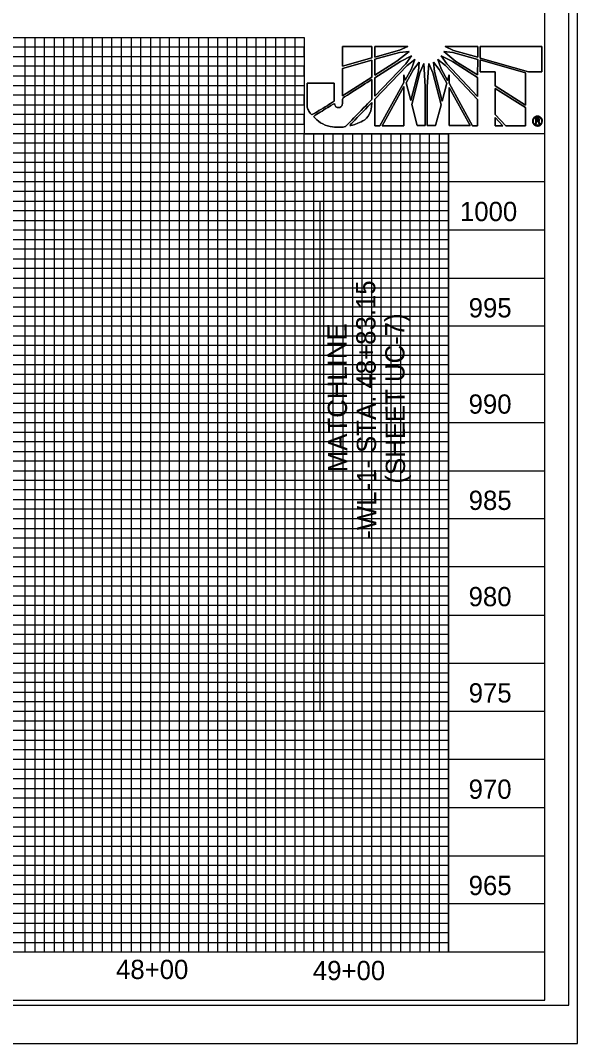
# Model space of a CAD drawing. Extents: x 0 to 7954, y -383 to 1504.
# Drawn here: x 2.351 to 2.833, y 0.008 to 0.894 of the extents above; entities that cross this region are included whole.
import ezdxf

# ---------------------------------------------------------------- set-up
doc = ezdxf.new("R2010")
doc.units = 0
for name, color, linetype in [('Layer 1', 7, 'Continuous'), ('Sheet Profile Grid Major CELL', 7, 'Continuous'), ('Sheet Profile Grid Middle', 7, 'Continuous'), ('Sheet Profile Grid Minor CELL', 7, 'Continuous'), ('UC Plan Profile Sheet 34 CELL', 7, 'Continuous'), ('UC Plan Sheet 34 CELL', 7, 'Continuous')]:
    doc.layers.add(name, color=color, linetype=linetype)

# ---------------------------------------------------------------- blocks, each defined once
blk = doc.blocks.new('block 2_1')
at = {"layer": 'Layer 1'}
for p, q in [((0.10682, 0.1325), (0.10682, 0.14026)), ((0.10682, 0.14026), (0.11852, 0.14026)), ((0.11852, 0.14026), (0.11852, 0.13575)), ((0.11973, 0.13613), (0.11973, 0.14032)), ((0.11973, 0.14032), (0.1329, 0.14032)), ((0.12954, 0.13884), (0.11973, 0.13613)), ((0.1329, 0.14032), (0.12954, 0.13884)), ((0.15109, 0.13878), (0.14781, 0.14032)), ((0.14781, 0.14032), (0.16078, 0.14026)), ((0.16078, 0.13606), (0.15109, 0.13878)), ((0.16078, 0.14026), (0.16078, 0.13606)), ((0.16169, 0.1358), (0.16169, 0.14032)), ((0.16169, 0.14032), (0.18629, 0.14032)), ((0.18629, 0.14032), (0.18629, 0.13024)), ((0.11852, 0.13575), (0.10682, 0.1325)), ((0.10682, 0.13161), (0.11852, 0.1349)), ((0.11852, 0.1349), (0.11852, 0.12812)), ((0.11973, 0.13523), (0.12954, 0.13793)), ((0.11973, 0.12889), (0.11973, 0.13523)), ((0.13337, 0.13839), (0.12852, 0.13445)), ((0.12954, 0.13793), (0.13337, 0.13839)), ((0.12987, 0.13432), (0.13433, 0.13658)), ((0.13433, 0.13658), (0.13207, 0.13341)), ((0.13257, 0.13277), (0.13568, 0.13517)), ((0.13568, 0.13517), (0.13425, 0.13142)), ((0.14476, 0.13517), (0.14787, 0.13277)), ((0.14619, 0.13142), (0.14476, 0.13517)), ((0.14613, 0.13658), (0.15065, 0.13432)), ((0.14839, 0.13335), (0.14613, 0.13658)), ((0.14715, 0.13839), (0.15076, 0.13793)), ((0.15206, 0.13438), (0.14715, 0.13839)), ((0.15076, 0.13793), (0.16078, 0.13517)), ((0.16078, 0.13517), (0.16071, 0.12897)), ((0.16169, 0.13567), (0.16169, 0.1358)), ((0.18106, 0.13024), (0.16169, 0.13567)), ((0.16169, 0.13497), (0.17982, 0.1298)), ((0.16169, 0.1349), (0.16169, 0.13497)), ((0.16169, 0.13019), (0.16169, 0.1349)), ((0.10682, 0.12071), (0.10682, 0.13161)), ((0.12852, 0.13445), (0.11973, 0.12889)), ((0.11973, 0.12787), (0.12987, 0.13432)), ((0.13207, 0.13341), (0.11973, 0.12057)), ((0.11973, 0.11933), (0.13257, 0.13277)), ((0.13425, 0.13142), (0.1318, 0.12696)), ((0.13213, 0.12586), (0.13505, 0.13115)), ((0.13505, 0.13115), (0.13736, 0.13412)), ((0.13736, 0.13412), (0.13704, 0.13051)), ((0.13769, 0.12986), (0.13929, 0.1336)), ((0.13929, 0.1336), (0.1398, 0.12437)), ((0.14063, 0.12437), (0.14123, 0.1336)), ((0.14123, 0.1336), (0.14277, 0.12986)), ((0.1431, 0.13412), (0.14536, 0.13115)), ((0.14348, 0.13038), (0.1431, 0.13412)), ((0.14536, 0.13115), (0.14839, 0.12567)), ((0.1487, 0.12677), (0.14619, 0.13142)), ((0.14787, 0.13277), (0.16071, 0.11922)), ((0.16071, 0.12043), (0.14839, 0.13335)), ((0.15065, 0.13432), (0.16071, 0.12793)), ((0.16071, 0.12897), (0.15206, 0.13438)), ((0.11852, 0.12812), (0.10682, 0.12071)), ((0.11973, 0.12057), (0.11973, 0.12787)), ((0.1318, 0.12696), (0.13122, 0.12908)), ((0.13122, 0.12908), (0.13122, 0.126)), ((0.13704, 0.13051), (0.134, 0.11883)), ((0.13439, 0.11721), (0.13769, 0.12986)), ((0.14277, 0.12986), (0.14613, 0.11702)), ((0.14652, 0.11856), (0.14348, 0.13038)), ((0.1493, 0.12908), (0.1487, 0.12677)), ((0.1493, 0.12567), (0.1493, 0.12908)), ((0.16071, 0.12793), (0.16071, 0.12043)), ((0.1677, 0.13019), (0.16169, 0.13019)), ((0.1677, 0.12457), (0.1677, 0.13019)), ((0.17982, 0.1298), (0.17982, 0.11688)), ((0.18629, 0.13024), (0.18106, 0.13024)), ((0.13122, 0.126), (0.12167, 0.10871)), ((0.12257, 0.10871), (0.13122, 0.12432)), ((0.13122, 0.12432), (0.1313, 0.10871)), ((0.134, 0.11883), (0.13213, 0.12586)), ((0.1398, 0.12437), (0.1398, 0.10877)), ((0.14063, 0.10877), (0.14063, 0.12437)), ((0.14839, 0.12567), (0.14652, 0.11856)), ((0.15864, 0.10871), (0.1493, 0.12567)), ((0.1493, 0.10877), (0.1493, 0.12399)), ((0.1493, 0.12399), (0.15768, 0.10877)), ((0.17982, 0.11688), (0.1677, 0.12457)), ((0.1677, 0.1236), (0.17982, 0.11597)), ((0.1677, 0.11314), (0.1677, 0.1236)), ((0.11973, 0.10871), (0.11973, 0.11933)), ((0.16071, 0.11922), (0.16071, 0.10871)), ((0.13659, 0.10877), (0.13439, 0.11721)), ((0.14613, 0.11702), (0.14387, 0.10877)), ((0.17982, 0.11597), (0.17982, 0.10871)), ((0.17189, 0.10871), (0.1677, 0.11314)), ((0.1677, 0.10871), (0.1677, 0.112)), ((0.1677, 0.112), (0.17073, 0.10871)), ((0.12167, 0.10871), (0.11973, 0.10871)), ((0.1313, 0.10871), (0.12257, 0.10871)), ((0.1398, 0.10877), (0.13659, 0.10877)), ((0.14387, 0.10877), (0.14063, 0.10877)), ((0.15768, 0.10877), (0.1493, 0.10877)), ((0.16071, 0.10871), (0.15864, 0.10871)), ((0.17073, 0.10871), (0.1677, 0.10871)), ((0.17982, 0.10871), (0.17189, 0.10871))]:
    blk.add_line(p, q, dxfattribs=at)
for points in [[(0.10682, 0.1325), (0.11852, 0.13575), (0.11852, 0.14026), (0.10682, 0.14026), (0.10682, 0.1325)], [(0.12954, 0.13884), (0.1329, 0.14032), (0.11973, 0.14032), (0.11973, 0.13613), (0.12954, 0.13884)], [(0.15109, 0.13878), (0.16078, 0.13606), (0.16078, 0.14026), (0.14781, 0.14032), (0.15109, 0.13878)], [(0.18629, 0.14032), (0.16169, 0.14032), (0.16169, 0.1358), (0.16169, 0.13567), (0.18106, 0.13024), (0.18629, 0.13024), (0.18629, 0.14032)], [(0.10682, 0.12071), (0.11852, 0.12812), (0.11852, 0.1349), (0.10682, 0.13161), (0.10682, 0.12071)], [(0.11973, 0.13523), (0.11973, 0.12889), (0.12852, 0.13445), (0.13337, 0.13839), (0.12954, 0.13793), (0.11973, 0.13523)], [(0.11973, 0.12787), (0.11973, 0.12057), (0.13207, 0.13341), (0.13433, 0.13658), (0.12987, 0.13432), (0.11973, 0.12787)], [(0.13568, 0.13517), (0.13257, 0.13277), (0.11973, 0.11933), (0.11973, 0.10871), (0.12167, 0.10871), (0.13122, 0.126), (0.13122, 0.12908), (0.1318, 0.12696), (0.13425, 0.13142), (0.13568, 0.13517)], [(0.14476, 0.13517), (0.14619, 0.13142), (0.1487, 0.12677), (0.1493, 0.12908), (0.1493, 0.12567), (0.15864, 0.10871), (0.16071, 0.10871), (0.16071, 0.11922), (0.14787, 0.13277), (0.14476, 0.13517)], [(0.14613, 0.13658), (0.14839, 0.13335), (0.16071, 0.12043), (0.16071, 0.12793), (0.15065, 0.13432), (0.14613, 0.13658)], [(0.14715, 0.13839), (0.15206, 0.13438), (0.16071, 0.12897), (0.16078, 0.13517), (0.15076, 0.13793), (0.14715, 0.13839)], [(0.16169, 0.13497), (0.16169, 0.1349), (0.16169, 0.13019), (0.1677, 0.13019), (0.1677, 0.12457), (0.17982, 0.11688), (0.17982, 0.1298), (0.16169, 0.13497)], [(0.13736, 0.13412), (0.13505, 0.13115), (0.13213, 0.12586), (0.134, 0.11883), (0.13704, 0.13051), (0.13736, 0.13412)], [(0.13769, 0.12986), (0.13439, 0.11721), (0.13659, 0.10877), (0.1398, 0.10877), (0.1398, 0.12437), (0.13929, 0.1336), (0.13769, 0.12986)], [(0.14123, 0.1336), (0.14063, 0.12437), (0.14063, 0.10877), (0.14387, 0.10877), (0.14613, 0.11702), (0.14277, 0.12986), (0.14123, 0.1336)], [(0.1431, 0.13412), (0.14348, 0.13038), (0.14652, 0.11856), (0.14839, 0.12567), (0.14536, 0.13115), (0.1431, 0.13412)], [(0.12257, 0.10871), (0.1313, 0.10871), (0.13122, 0.12432), (0.12257, 0.10871)], [(0.1493, 0.10877), (0.15768, 0.10877), (0.1493, 0.12399), (0.1493, 0.10877)], [(0.1677, 0.1236), (0.1677, 0.11314), (0.17189, 0.10871), (0.17982, 0.10871), (0.17982, 0.11597), (0.1677, 0.1236), (0.1677, 0.1236)], [(0.1677, 0.10871), (0.1677, 0.10871), (0.17073, 0.10871), (0.1677, 0.112), (0.1677, 0.10871)], [(0.18456, 0.11147), (0.18383, 0.11147), (0.18383, 0.10968), (0.18424, 0.10968), (0.18424, 0.11038), (0.18456, 0.11038), (0.18456, 0.1107), (0.18424, 0.1107), (0.18424, 0.11113), (0.18456, 0.11113), (0.18456, 0.11147)], [(0.18456, 0.11147), (0.18383, 0.11147), (0.18383, 0.10968), (0.18424, 0.10968), (0.18424, 0.11038), (0.18456, 0.11038)], [(0.18456, 0.1107), (0.18424, 0.1107), (0.18424, 0.11113), (0.18456, 0.11113)]]:
    blk.add_lwpolyline(points, dxfattribs=at)
for points in [[(0.10514, 0.11597), (0.10444, 0.11597), (0.10384, 0.11636), (0.10359, 0.11765), (0.10359, 0.11765), (0.09519, 0.11246), (0.09519, 0.11246), (0.09778, 0.10974), (0.10191, 0.10812), (0.10541, 0.10812), (0.10632, 0.10812), (0.10701, 0.10819), (0.10798, 0.10839), (0.10798, 0.10839), (0.11852, 0.11928), (0.11852, 0.11928), (0.11852, 0.11928), (0.11852, 0.12715), (0.11852, 0.12715), (0.11852, 0.12715), (0.10682, 0.11972), (0.10682, 0.11972), (0.10682, 0.11677), (0.1061, 0.11597), (0.10514, 0.11597)], [(0.10514, 0.11597), (0.1061, 0.11597), (0.10682, 0.11677), (0.10682, 0.11972), (0.10682, 0.11972), (0.11852, 0.12715), (0.11852, 0.12715), (0.11852, 0.12715), (0.11852, 0.11928), (0.11852, 0.11928), (0.11852, 0.11928), (0.10798, 0.10839), (0.10798, 0.10839), (0.10701, 0.10819), (0.10632, 0.10812), (0.10541, 0.10812), (0.10191, 0.10812), (0.09778, 0.10974), (0.09519, 0.11246), (0.09519, 0.11246), (0.10359, 0.11765), (0.10359, 0.11765), (0.10384, 0.11636), (0.10444, 0.11597), (0.10514, 0.11597)], [(0.10346, 0.12573), (0.10346, 0.12573), (0.09263, 0.12573), (0.09263, 0.12573), (0.09263, 0.12573), (0.09263, 0.11895), (0.09263, 0.11895), (0.09263, 0.11895), (0.09263, 0.11823), (0.09263, 0.11823), (0.09263, 0.11611), (0.09332, 0.11443), (0.09456, 0.11302), (0.09456, 0.11302), (0.10346, 0.11843), (0.10346, 0.11856), (0.10346, 0.11856), (0.10346, 0.12573), (0.10346, 0.12573)], [(0.10346, 0.12573), (0.10346, 0.12573), (0.10346, 0.11856), (0.10346, 0.11856), (0.10346, 0.11843), (0.09456, 0.11302), (0.09456, 0.11302), (0.09332, 0.11443), (0.09263, 0.11611), (0.09263, 0.11823), (0.09263, 0.11823), (0.09263, 0.11895), (0.09263, 0.11895), (0.09263, 0.11895), (0.09263, 0.12573), (0.09263, 0.12573), (0.09263, 0.12573), (0.10346, 0.12573), (0.10346, 0.12573)], [(0.11852, 0.11804), (0.11852, 0.11804), (0.1094, 0.10864), (0.1094, 0.10864), (0.11386, 0.10974), (0.11831, 0.11269), (0.11852, 0.11804)], [(0.11852, 0.11804), (0.11831, 0.11269), (0.11386, 0.10974), (0.1094, 0.10864), (0.1094, 0.10864), (0.11852, 0.11804), (0.11852, 0.11804)], [(0.18456, 0.10859), (0.18403, 0.10859), (0.18355, 0.10878), (0.18316, 0.10917), (0.18277, 0.10955), (0.18258, 0.11002), (0.18258, 0.11057), (0.18258, 0.11113), (0.18277, 0.1116), (0.18316, 0.11195), (0.18355, 0.11233), (0.18401, 0.11252), (0.18456, 0.11252), (0.18456, 0.11252), (0.18456, 0.11215), (0.18456, 0.11215), (0.18412, 0.11215), (0.18375, 0.112), (0.18344, 0.11171), (0.18313, 0.1114), (0.18297, 0.11101), (0.18297, 0.11057), (0.18297, 0.11013), (0.18313, 0.10974), (0.18344, 0.10943), (0.18375, 0.10913), (0.18412, 0.10898), (0.18456, 0.10898), (0.18456, 0.10898), (0.18456, 0.10859), (0.18456, 0.10859), (0.18456, 0.10859), (0.18456, 0.10859), (0.18456, 0.10859)], [(0.18456, 0.11252), (0.18401, 0.11252), (0.18355, 0.11233), (0.18316, 0.11195), (0.18277, 0.1116), (0.18258, 0.11113), (0.18258, 0.11057), (0.18258, 0.11002), (0.18277, 0.10955), (0.18316, 0.10917), (0.18355, 0.10878), (0.18403, 0.10859), (0.18456, 0.10859)], [(0.18456, 0.10898), (0.18412, 0.10898), (0.18375, 0.10913), (0.18344, 0.10943), (0.18313, 0.10974), (0.18297, 0.11013), (0.18297, 0.11057), (0.18297, 0.11101), (0.18313, 0.1114), (0.18344, 0.11171), (0.18375, 0.112), (0.18412, 0.11215), (0.18456, 0.11215)], [(0.18656, 0.11057), (0.18656, 0.11002), (0.18637, 0.10955), (0.18599, 0.10916), (0.1856, 0.10878), (0.18513, 0.10859), (0.18458, 0.10859), (0.18458, 0.10859), (0.18458, 0.10859), (0.18456, 0.10859), (0.18456, 0.10859), (0.18456, 0.10898), (0.18456, 0.10898), (0.18458, 0.10898), (0.18458, 0.10898), (0.18458, 0.10898), (0.18502, 0.10898), (0.18539, 0.10913), (0.1857, 0.10943), (0.18601, 0.10974), (0.18617, 0.11013), (0.18617, 0.11057), (0.18617, 0.11101), (0.18601, 0.1114), (0.1857, 0.11171), (0.18539, 0.112), (0.18502, 0.11215), (0.18456, 0.11215), (0.18456, 0.11215), (0.18456, 0.11252), (0.18456, 0.11252), (0.18512, 0.11252), (0.18559, 0.11233), (0.18598, 0.11195), (0.18637, 0.1116), (0.18656, 0.11113), (0.18656, 0.11057), (0.18656, 0.11057), (0.18656, 0.11057), (0.18656, 0.11057)], [(0.18656, 0.11057), (0.18656, 0.11113), (0.18637, 0.1116), (0.18598, 0.11195), (0.18559, 0.11233), (0.18512, 0.11252), (0.18456, 0.11252)], [(0.18456, 0.11215), (0.18502, 0.11215), (0.18539, 0.112), (0.1857, 0.11171), (0.18601, 0.1114), (0.18617, 0.11101), (0.18617, 0.11057), (0.18617, 0.11013), (0.18601, 0.10974), (0.1857, 0.10943), (0.18539, 0.10913), (0.18502, 0.10898), (0.18458, 0.10898), (0.18458, 0.10898), (0.18458, 0.10898), (0.18456, 0.10898)], [(0.18456, 0.11038), (0.18456, 0.11038), (0.18456, 0.1107), (0.18456, 0.1107), (0.18456, 0.1107), (0.18458, 0.1107), (0.18458, 0.1107), (0.18484, 0.1107), (0.18497, 0.11078), (0.18497, 0.11093), (0.18497, 0.11106), (0.18485, 0.11113), (0.18461, 0.11113), (0.18461, 0.11113), (0.18456, 0.11113), (0.18456, 0.11113), (0.18456, 0.11113), (0.18456, 0.11147), (0.18456, 0.11147), (0.18456, 0.11147), (0.18468, 0.11147), (0.18468, 0.11147), (0.18513, 0.11147), (0.18536, 0.11129), (0.18536, 0.11093), (0.18536, 0.11077), (0.18529, 0.11064), (0.18515, 0.11054), (0.18526, 0.11048), (0.18533, 0.11033), (0.18534, 0.1101), (0.18534, 0.1101), (0.18534, 0.11), (0.18534, 0.11), (0.18534, 0.11), (0.18536, 0.10994), (0.18536, 0.10994), (0.18536, 0.10994), (0.18536, 0.10987), (0.18536, 0.10987), (0.18536, 0.10987), (0.18541, 0.10968), (0.18541, 0.10968), (0.18541, 0.10968), (0.18503, 0.10968), (0.18503, 0.10968), (0.18499, 0.10978), (0.18495, 0.10987), (0.18495, 0.11), (0.18495, 0.11017), (0.18494, 0.11026), (0.18489, 0.11031), (0.18484, 0.11034), (0.18474, 0.11038), (0.18458, 0.11038), (0.18458, 0.11038), (0.18456, 0.11038), (0.18456, 0.11038)], [(0.18456, 0.11038), (0.18456, 0.11038), (0.18458, 0.11038), (0.18458, 0.11038), (0.18474, 0.11038), (0.18484, 0.11034), (0.18489, 0.11031), (0.18494, 0.11026), (0.18495, 0.11017), (0.18495, 0.11), (0.18495, 0.10987), (0.18499, 0.10978), (0.18503, 0.10968), (0.18503, 0.10968), (0.18541, 0.10968), (0.18541, 0.10968), (0.18541, 0.10968), (0.18536, 0.10987), (0.18536, 0.10987), (0.18536, 0.10987), (0.18536, 0.10994), (0.18536, 0.10994), (0.18536, 0.10994), (0.18534, 0.11), (0.18534, 0.11), (0.18534, 0.11), (0.18534, 0.1101), (0.18534, 0.1101), (0.18533, 0.11033), (0.18526, 0.11048), (0.18515, 0.11054), (0.18529, 0.11064), (0.18536, 0.11077), (0.18536, 0.11093), (0.18536, 0.11129), (0.18513, 0.11147), (0.18468, 0.11147), (0.18468, 0.11147), (0.18456, 0.11147), (0.18456, 0.11147)], [(0.18456, 0.11113), (0.18456, 0.11113), (0.18461, 0.11113), (0.18461, 0.11113), (0.18485, 0.11113), (0.18497, 0.11106), (0.18497, 0.11093), (0.18497, 0.11078), (0.18484, 0.1107), (0.18458, 0.1107), (0.18458, 0.1107), (0.18456, 0.1107), (0.18456, 0.1107)], [(0.18456, 0.10859), (0.18458, 0.10859), (0.18458, 0.10859), (0.18458, 0.10859), (0.18513, 0.10859), (0.1856, 0.10878), (0.18599, 0.10916), (0.18637, 0.10955), (0.18656, 0.11002), (0.18656, 0.11057)]]:
    blk.add_open_spline(points, degree=3, dxfattribs=at)

msp = doc.modelspace()

# ---------------------------------------------------------------- linework, layer by layer
at = {"layer": 'Sheet Profile Grid Major CELL'}
for points in [[(0.30499, 0.87916), (2.59666, 0.87916)], [(2.38833, 0.0875), (2.38833, 0.87916), (2.47166, 0.87916), (2.47166, 0.0875)], [(2.55499, 0.0875), (2.55499, 0.87916), (2.59666, 0.87916), (2.59666, 0.79583), (2.63833, 0.79583), (2.63833, 0.0875)], [(2.80499, 0.79583), (0.30499, 0.79583), (0.30499, 0.7125), (2.80499, 0.7125)], [(2.72166, 0.0875), (2.72166, 0.79583)], [(2.80499, 0.62916), (0.30499, 0.62916), (0.30499, 0.54583), (2.80499, 0.54583)], [(2.80499, 0.4625), (0.30499, 0.4625), (0.30499, 0.37916), (2.80499, 0.37916)], [(2.80499, 0.29583), (0.30499, 0.29583), (0.30499, 0.2125), (2.80499, 0.2125)], [(2.80499, 0.12916), (0.30499, 0.12916)]]:
    msp.add_lwpolyline(points, dxfattribs=at)
at = {"layer": 'Sheet Profile Grid Middle'}
for p, q in [((0.30499, 0.8375), (2.59666, 0.8375)), ((2.80499, 0.75416), (0.30499, 0.75416)), ((0.30499, 0.67083), (2.80499, 0.67083)), ((2.80499, 0.5875), (0.30499, 0.5875)), ((0.30499, 0.50416), (2.80499, 0.50416)), ((2.80499, 0.42083), (0.30499, 0.42083)), ((0.30499, 0.3375), (2.80499, 0.3375)), ((2.80499, 0.25416), (0.30499, 0.25416)), ((0.30499, 0.17083), (2.80499, 0.17083))]:
    msp.add_line(p, q, dxfattribs=at)
for points in [[(2.42999, 0.0875), (2.42999, 0.87916), (2.51333, 0.87916), (2.51333, 0.0875)], [(2.59666, 0.0875), (2.59666, 0.79583), (2.67999, 0.79583), (2.67999, 0.0875)]]:
    msp.add_lwpolyline(points, dxfattribs=at)
at = {"layer": 'Sheet Profile Grid Minor CELL'}
for points in [[(2.35499, 0.0875), (2.35499, 0.87916), (2.36333, 0.87916), (2.36333, 0.0875)], [(2.37166, 0.0875), (2.37166, 0.87916), (2.37999, 0.87916), (2.37999, 0.0875)], [(2.39666, 0.0875), (2.39666, 0.87916), (2.40499, 0.87916), (2.40499, 0.0875)], [(2.41333, 0.0875), (2.41333, 0.87916), (2.42166, 0.87916), (2.42166, 0.0875)], [(2.43833, 0.0875), (2.43833, 0.87916), (2.44666, 0.87916), (2.44666, 0.0875)], [(2.45499, 0.0875), (2.45499, 0.87916), (2.46333, 0.87916), (2.46333, 0.0875)], [(2.47999, 0.0875), (2.47999, 0.87916), (2.48833, 0.87916), (2.48833, 0.0875)], [(2.49666, 0.0875), (2.49666, 0.87916), (2.50499, 0.87916), (2.50499, 0.0875)], [(2.52166, 0.0875), (2.52166, 0.87916), (2.52999, 0.87916), (2.52999, 0.0875)], [(2.53833, 0.0875), (2.53833, 0.87916), (2.54666, 0.87916), (2.54666, 0.0875)], [(2.56333, 0.0875), (2.56333, 0.87916), (2.57166, 0.87916), (2.57166, 0.0875)], [(2.57999, 0.0875), (2.57999, 0.87916), (2.58833, 0.87916), (2.58833, 0.0875)], [(0.38833, 0.8625), (2.59666, 0.8625), (2.59666, 0.87083), (0.38833, 0.87083)], [(0.38833, 0.84583), (2.59666, 0.84583), (2.59666, 0.85416), (0.38833, 0.85416)], [(0.38833, 0.82083), (2.59666, 0.82083), (2.59666, 0.82916), (0.38833, 0.82916)], [(0.38833, 0.80416), (2.59666, 0.80416), (2.59666, 0.8125), (0.38833, 0.8125)], [(2.60499, 0.0875), (2.60499, 0.79583), (2.61333, 0.79583), (2.61333, 0.0875)], [(2.62166, 0.0875), (2.62166, 0.79583), (2.62999, 0.79583), (2.62999, 0.0875)], [(2.64666, 0.0875), (2.64666, 0.79583), (2.65499, 0.79583), (2.65499, 0.0875)], [(2.66333, 0.0875), (2.66333, 0.79583), (2.67166, 0.79583), (2.67166, 0.0875)], [(2.68833, 0.0875), (2.68833, 0.79583), (2.69666, 0.79583), (2.69666, 0.0875)], [(2.70499, 0.0875), (2.70499, 0.79583), (2.71333, 0.79583), (2.71333, 0.0875)], [(0.38833, 0.77916), (2.72166, 0.77916), (2.72166, 0.7875), (0.38833, 0.7875)], [(0.38833, 0.7625), (2.72166, 0.7625), (2.72166, 0.77083), (0.38833, 0.77083)], [(0.38833, 0.7375), (2.72166, 0.7375), (2.72166, 0.74583), (0.38833, 0.74583)], [(0.38833, 0.72083), (2.72166, 0.72083), (2.72166, 0.72916), (0.38833, 0.72916)], [(0.38833, 0.70416), (2.72166, 0.70416)], [(0.38833, 0.6875), (2.72166, 0.6875), (2.72166, 0.69583), (0.38833, 0.69583)], [(0.38833, 0.6625), (2.72166, 0.6625), (2.72166, 0.67916), (0.38833, 0.67916)], [(0.38833, 0.64583), (2.72166, 0.64583), (2.72166, 0.65416), (0.38833, 0.65416)], [(0.38833, 0.62083), (2.72166, 0.62083), (2.72166, 0.6375), (0.38833, 0.6375)], [(0.38833, 0.60416), (2.72166, 0.60416), (2.72166, 0.6125), (0.38833, 0.6125)], [(0.38833, 0.57916), (2.72166, 0.57916), (2.72166, 0.59583), (0.38833, 0.59583)], [(0.38833, 0.5625), (2.72166, 0.5625), (2.72166, 0.57083), (0.38833, 0.57083)], [(0.38833, 0.5375), (2.72166, 0.5375), (2.72166, 0.55416), (0.38833, 0.55416)], [(0.38833, 0.52083), (2.72166, 0.52083), (2.72166, 0.52916), (0.38833, 0.52916)], [(0.38833, 0.49583), (2.72166, 0.49583), (2.72166, 0.5125), (0.38833, 0.5125)], [(0.38833, 0.47916), (2.72166, 0.47916), (2.72166, 0.4875), (0.38833, 0.4875)], [(0.38833, 0.45416), (2.72166, 0.45416), (2.72166, 0.47083), (0.38833, 0.47083)], [(0.38833, 0.4375), (2.72166, 0.4375), (2.72166, 0.44583), (0.38833, 0.44583)], [(0.38833, 0.4125), (2.72166, 0.4125), (2.72166, 0.42916), (0.38833, 0.42916)], [(0.38833, 0.39583), (2.72166, 0.39583), (2.72166, 0.40416), (0.38833, 0.40416)], [(0.38833, 0.37083), (2.72166, 0.37083), (2.72166, 0.3875), (0.38833, 0.3875)], [(0.38833, 0.35416), (2.72166, 0.35416), (2.72166, 0.3625), (0.38833, 0.3625)], [(0.38833, 0.32916), (2.72166, 0.32916), (2.72166, 0.34583), (0.38833, 0.34583)], [(0.38833, 0.3125), (2.72166, 0.3125), (2.72166, 0.32083), (0.38833, 0.32083)], [(0.38833, 0.2875), (2.72166, 0.2875), (2.72166, 0.30416), (0.38833, 0.30416)], [(0.38833, 0.27083), (2.72166, 0.27083), (2.72166, 0.27916), (0.38833, 0.27916)], [(0.38833, 0.24583), (2.72166, 0.24583), (2.72166, 0.2625), (0.38833, 0.2625)], [(0.38833, 0.22916), (2.72166, 0.22916), (2.72166, 0.2375), (0.38833, 0.2375)], [(0.38833, 0.20416), (2.72166, 0.20416), (2.72166, 0.22083), (0.38833, 0.22083)], [(0.38833, 0.09583), (2.72166, 0.09583), (2.72166, 0.10416), (0.38833, 0.10416), (0.38833, 0.1125), (2.72166, 0.1125), (2.72166, 0.12083), (0.38833, 0.12083), (0.38833, 0.12916), (0.38833, 0.1375), (2.72166, 0.1375), (2.72166, 0.14583), (0.38833, 0.14583), (0.38833, 0.15416), (2.72166, 0.15416), (2.72166, 0.1625), (0.38833, 0.1625), (0.38833, 0.17083), (0.38833, 0.17916), (2.72166, 0.17916), (2.72166, 0.1875), (0.38833, 0.1875), (0.38833, 0.19583), (2.72166, 0.19583)]]:
    msp.add_lwpolyline(points, dxfattribs=at)
at = {"layer": 'UC Plan Profile Sheet 34 CELL'}
for p, q in [((2.61025, 0.7375), (2.61025, 0.29583)), ((2.80499, 0.0875), (0.30499, 0.0875))]:
    msp.add_line(p, q, dxfattribs=at)
for points in [[(0.02749, 0.00833), (2.83333, 0.00833), (2.83333, 1.83333), (0.02749, 1.83333)], [(0.04916, 0.04166), (2.82583, 0.04166), (2.82583, 1.8), (0.04916, 1.8)], [(2.80499, 1.79583), (0.30499, 1.79583), (0.30499, 0.04583), (2.80499, 0.04583)], [(0.38833, 0.87916), (2.59666, 0.87916), (2.59666, 0.79583), (2.72166, 0.79583), (2.72166, 0.0875), (0.38833, 0.0875)]]:
    msp.add_lwpolyline(points, close=True, dxfattribs=at)

# ---------------------------------------------------------------- block references
at = {"layer": 'UC Plan Sheet 34 CELL', "xscale": 2.170686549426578, "yscale": 2.170686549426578}
msp.add_blockref('block 2_1', (2.39796, 0.56671), dxfattribs=at)

# ---------------------------------------------------------------- texts
at = {"layer": 'UC Plan Profile Sheet 34 CELL'}
for s, p in [('1000', (2.73148, 0.72017)), ('995', (2.73904, 0.63683)), ('990', (2.73898, 0.5535)), ('985', (2.73904, 0.47017)), ('980', (2.73898, 0.38683)), ('975', (2.73904, 0.3035)), ('970', (2.73898, 0.22017)), ('965', (2.73904, 0.13683)), ('48+00', (2.43363, 0.06416)), ('49+00', (2.6041, 0.0632))]:
    msp.add_text(s, height=0.016667, dxfattribs=at).set_placement(p)
for s, height, p in [('-WL-1- STA. 48+83.15', 0.0166667, (2.65918, 0.4453)), ('(SHEET UC-7)', 0.0166667, (2.68396, 0.49302)), ('MATCHLINE ', 0.016667, (2.63391, 0.50289))]:
    msp.add_text(s, height=height, rotation=90.27103, dxfattribs=at).set_placement(p)

doc.saveas('drawing.dxf')
